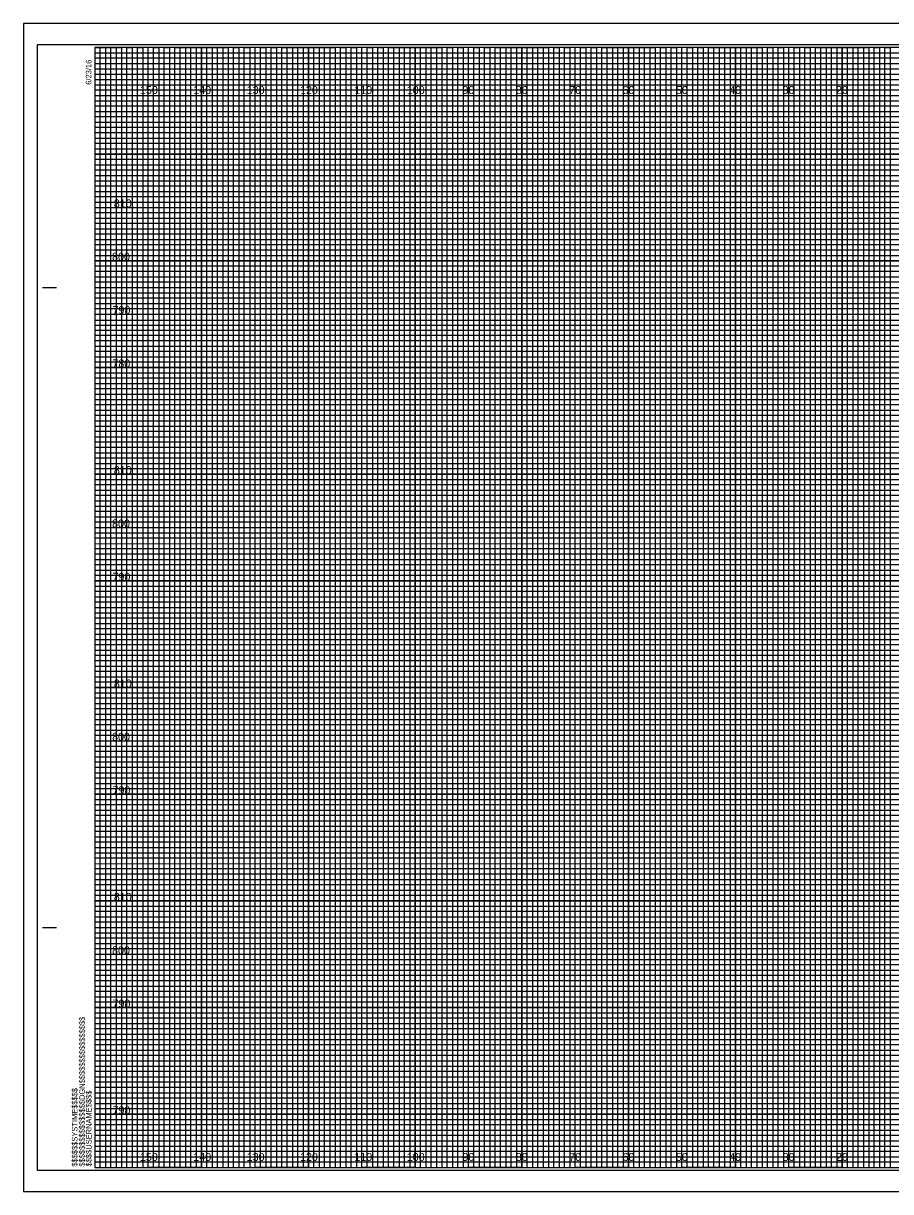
# Model space of a CAD drawing. Extents: x -13 to 323, y -4 to 214.
# Drawn here: x -13.4 to 149.1, y -4.5 to 214.5 of the extents above; entities that cross this region are included whole.
import ezdxf

# ---------------------------------------------------------------- set-up
doc = ezdxf.new("R2010")
doc.units = 0
for name, color, linetype in [('Exist Cross Section Cell', 7, 'Continuous'), ('Exist XS Center Line Elevation Label', 7, 'Continuous'), ('Exist XS Ground Line', 7, 'Continuous'), ('Prop CMT Pvmt Course 2', 7, 'Continuous'), ('Prop CMT Pvmt Course 3', 7, 'Continuous'), ('Prop CMT Pvmt Surface', 7, 'Continuous'), ('Prop CMT Shld Paved Course 1', 7, 'Continuous'), ('Prop CMT Shld Paved Course 3', 7, 'Continuous'), ('Prop CMT Subgrade Earthwork', 7, 'Continuous'), ('Scratch_Level_4', 7, 'Continuous'), ('Scratch_Level_7', 7, 'Continuous')]:
    doc.layers.add(name, color=color, linetype=linetype)

msp = doc.modelspace()

# ---------------------------------------------------------------- linework, layer by layer
at = {"layer": 'Exist XS Center Line Elevation Label'}
for points in [[(0, 210), (5, 210), (5, 0), (15, 0), (15, 210), (25, 210), (25, 0), (35, 0), (35, 210), (45, 210), (45, 0), (55, 0), (55, 210), (65, 210), (65, 0), (75, 0), (75, 210), (85, 210), (85, 0), (95, 0), (95, 210), (105, 210), (105, 0), (115, 0), (115, 210), (125, 210), (125, 0), (135, 0), (135, 210), (145, 210), (145, 0), (155, 0)], [(0, 205), (275, 205)], [(0, 185), (320, 185), (320, 195), (0, 195)], [(0, 165), (320, 165), (320, 175), (0, 175)], [(0, 145), (320, 145), (320, 155), (0, 155)], [(0, 125), (320, 125), (320, 135), (0, 135)], [(0, 105), (320, 105), (320, 115), (0, 115)], [(0, 85), (320, 85), (320, 95), (0, 95)], [(0, 65), (320, 65), (320, 75), (0, 75)], [(0, 45), (320, 45), (320, 55), (0, 55)], [(0, 25), (320, 25), (320, 35), (0, 35)], [(0, 5), (320, 5), (320, 15), (0, 15)]]:
    msp.add_lwpolyline(points, dxfattribs=at)
at = {"layer": 'Exist XS Ground Line'}
for p, q in [((10, 210), (0, 210)), ((10, 0), (10, 210)), ((30, 210), (20, 210)), ((20, 210), (20, 0)), ((30, 0), (30, 210)), ((50, 210), (40, 210)), ((40, 210), (40, 0)), ((50, 0), (50, 210)), ((70, 210), (60, 210)), ((60, 210), (60, 0)), ((70, 0), (70, 210)), ((90, 210), (80, 210)), ((80, 210), (80, 0)), ((90, 0), (90, 210)), ((110, 210), (100, 210)), ((100, 210), (100, 0)), ((110, 0), (110, 210)), ((130, 210), (120, 210)), ((120, 210), (120, 0)), ((130, 0), (130, 210)), ((150, 210), (140, 210)), ((140, 210), (140, 0)), ((20, 0), (10, 0)), ((40, 0), (30, 0)), ((60, 0), (50, 0)), ((80, 0), (70, 0)), ((100, 0), (90, 0)), ((120, 0), (110, 0)), ((140, 0), (130, 0))]:
    msp.add_line(p, q, dxfattribs=at)
for points in [[(0, 200), (320, 200), (320, 190), (0, 190)], [(0, 180), (320, 180), (320, 170), (0, 170)], [(0, 160), (320, 160), (320, 150), (0, 150)], [(0, 140), (320, 140), (320, 130), (0, 130)], [(0, 120), (320, 120), (320, 110), (0, 110)], [(0, 100), (320, 100), (320, 90), (0, 90)], [(0, 80), (320, 80), (320, 70), (0, 70)], [(0, 60), (320, 60), (320, 50), (0, 50)], [(0, 40), (320, 40), (320, 30), (0, 30)], [(0, 20), (320, 20), (320, 10), (0, 10)]]:
    msp.add_lwpolyline(points, dxfattribs=at)
at = {"layer": 'Prop CMT Pvmt Course 2'}
msp.add_lwpolyline([(-10.8, -0.5), (322.4, -0.5), (322.4, 210.5), (-10.8, 210.5)], close=True, dxfattribs=at)
at = {"layer": 'Prop CMT Pvmt Course 3'}
for p, q in [((10, 0), (10, 210)), ((20, 0), (20, 210)), ((30, 0), (30, 210)), ((40, 0), (40, 210)), ((50, 0), (50, 210)), ((60, 0), (60, 210)), ((70, 0), (70, 210)), ((80, 0), (80, 210)), ((90, 0), (90, 210)), ((100, 0), (100, 210)), ((110, 0), (110, 210)), ((120, 0), (120, 210)), ((130, 0), (130, 210)), ((140, 0), (140, 210)), ((0, 200), (320, 200)), ((0, 190), (320, 190)), ((0, 180), (320, 180)), ((0, 170), (320, 170)), ((0, 160), (320, 160)), ((0, 150), (320, 150)), ((0, 140), (320, 140)), ((0, 130), (320, 130)), ((0, 120), (320, 120)), ((0, 110), (320, 110)), ((0, 100), (320, 100)), ((0, 90), (320, 90)), ((0, 80), (320, 80)), ((0, 70), (320, 70)), ((0, 60), (320, 60)), ((0, 50), (320, 50)), ((0, 40), (320, 40)), ((0, 30), (320, 30)), ((0, 20), (320, 20)), ((0, 10), (320, 10))]:
    msp.add_line(p, q, dxfattribs=at)
at = {"layer": 'Prop CMT Shld Paved Course 1'}
for points in [[(0, 0), (1, 0), (1, 210), (2, 210), (2, 0)], [(2, 0), (3, 0), (3, 210), (4, 210), (4, 0)], [(5, 0), (6, 0), (6, 210), (7, 210), (7, 0)], [(7, 0), (8, 0), (8, 210), (9, 210), (9, 0)], [(10, 0), (11, 0), (11, 210), (12, 210), (12, 0)], [(12, 0), (13, 0), (13, 210), (14, 210), (14, 0)], [(15, 0), (16, 0), (16, 210), (17, 210), (17, 0)], [(17, 0), (18, 0), (18, 210), (19, 210), (19, 0)], [(20, 0), (21, 0), (21, 210), (22, 210), (22, 0)], [(22, 0), (23, 0), (23, 210), (24, 210), (24, 0)], [(25, 0), (26, 0), (26, 210), (27, 210), (27, 0)], [(27, 0), (28, 0), (28, 210), (29, 210), (29, 0)], [(30, 0), (31, 0), (31, 210), (32, 210), (32, 0)], [(32, 0), (33, 0), (33, 210), (34, 210), (34, 0)], [(35, 0), (36, 0), (36, 210), (37, 210), (37, 0)], [(37, 0), (38, 0), (38, 210), (39, 210), (39, 0)], [(40, 0), (41, 0), (41, 210), (42, 210), (42, 0)], [(42, 0), (43, 0), (43, 210), (44, 210), (44, 0)], [(45, 0), (46, 0), (46, 210), (47, 210), (47, 0)], [(47, 0), (48, 0), (48, 210), (49, 210), (49, 0)], [(50, 0), (51, 0), (51, 210), (52, 210), (52, 0)], [(52, 0), (53, 0), (53, 210), (54, 210), (54, 0)], [(55, 0), (56, 0), (56, 210), (57, 210), (57, 0)], [(57, 0), (58, 0), (58, 210), (59, 210), (59, 0)], [(60, 0), (61, 0), (61, 210), (62, 210), (62, 0)], [(62, 0), (63, 0), (63, 210), (64, 210), (64, 0)], [(65, 0), (66, 0), (66, 210), (67, 210), (67, 0)], [(67, 0), (68, 0), (68, 210), (69, 210), (69, 0)], [(70, 0), (71, 0), (71, 210), (72, 210), (72, 0)], [(72, 0), (73, 0), (73, 210), (74, 210), (74, 0)], [(75, 0), (76, 0), (76, 210), (77, 210), (77, 0)], [(77, 0), (78, 0), (78, 210), (79, 210), (79, 0)], [(80, 0), (81, 0), (81, 210), (82, 210), (82, 0)], [(82, 0), (83, 0), (83, 210), (84, 210), (84, 0)], [(85, 0), (86, 0), (86, 210), (87, 210), (87, 0)], [(87, 0), (88, 0), (88, 210), (89, 210), (89, 0)], [(90, 0), (91, 0), (91, 210), (92, 210), (92, 0)], [(92, 0), (93, 0), (93, 210), (94, 210), (94, 0)], [(95, 0), (96, 0), (96, 210), (97, 210), (97, 0)], [(97, 0), (98, 0), (98, 210), (99, 210), (99, 0)], [(100, 0), (101, 0), (101, 210), (102, 210), (102, 0)], [(102, 0), (103, 0), (103, 210), (104, 210), (104, 0)], [(105, 0), (106, 0), (106, 210), (107, 210), (107, 0)], [(107, 0), (108, 0), (108, 210), (109, 210), (109, 0)], [(110, 0), (111, 0), (111, 210), (112, 210), (112, 0)], [(112, 0), (113, 0), (113, 210), (114, 210), (114, 0)], [(115, 0), (116, 0), (116, 210), (117, 210), (117, 0)], [(117, 0), (118, 0), (118, 210), (119, 210), (119, 0)], [(120, 0), (121, 0), (121, 210), (122, 210), (122, 0)], [(122, 0), (123, 0), (123, 210), (124, 210), (124, 0)], [(125, 0), (126, 0), (126, 210), (127, 210), (127, 0)], [(127, 0), (128, 0), (128, 210), (129, 210), (129, 0)], [(130, 0), (131, 0), (131, 210), (132, 210), (132, 0)], [(132, 0), (133, 0), (133, 210), (134, 210), (134, 0)], [(135, 0), (136, 0), (136, 210), (137, 210), (137, 0)], [(137, 0), (138, 0), (138, 210), (139, 210), (139, 0)], [(140, 0), (141, 0), (141, 210), (142, 210), (142, 0)], [(142, 0), (143, 0), (143, 210), (144, 210), (144, 0)], [(145, 0), (146, 0), (146, 210), (147, 210), (147, 0)], [(147, 0), (148, 0), (148, 210), (149, 210), (149, 0)]]:
    msp.add_lwpolyline(points, dxfattribs=at)
at = {"layer": 'Prop CMT Shld Paved Course 3'}
msp.add_lwpolyline([(-13.4, -4.5), (323.3, -4.5), (323.3, 214.5), (-13.4, 214.5)], close=True, dxfattribs=at)
at = {"layer": 'Prop CMT Subgrade Earthwork'}
for p, q in [((323.3, 214.5), (-13.4, 214.5)), ((-13.4, 214.5), (-13.4, -4.5)), ((-13.4, -4.5), (323.3, -4.5))]:
    msp.add_line(p, q, dxfattribs=at)
at = {"layer": 'Scratch_Level_4'}
for p, q in [((0, 209), (260, 209)), ((260, 207.98), (0, 207.98)), ((0, 207.98), (0, 207)), ((0, 207), (260, 207)), ((260, 205.89), (0, 205.89)), ((0, 205.89), (0, 204)), ((0, 204), (320, 204))]:
    msp.add_line(p, q, dxfattribs=at)
for points in [[(0, 203), (270, 203), (320, 203), (320, 202), (0, 202)], [(0, 201), (320, 201), (320, 199), (0, 199)], [(0, 198), (320, 198), (320, 197), (0, 196.98)], [(0, 196), (320, 196), (320, 194), (0, 194)], [(0, 193), (320, 193), (320, 192), (0, 192)], [(0, 191), (320, 191), (320, 189), (0, 189)], [(0, 188), (320, 188), (320, 187), (0, 187)], [(0, 186), (320, 186), (320, 184), (0, 184)], [(0, 183), (320, 183), (320, 182), (0, 182)], [(0, 181), (320, 181), (320, 179), (0, 179)], [(0, 178), (320, 178), (320, 177), (0, 177)], [(0, 176), (320, 176), (320, 173.95), (320, 173), (320, 172), (0, 172)], [(0, 174), (320, 174), (320, 173), (0, 173)], [(0, 171), (320, 171), (320, 169), (0, 169.03)], [(0, 169.03), (320, 169), (320, 168), (0, 168)], [(0, 167), (320, 167), (320, 166), (0, 166)], [(0, 164), (320, 164), (320, 163), (0, 163)], [(0, 162), (320, 162), (320, 161), (0, 161)], [(-0.07, 158.89), (320, 158.89), (320, 157.88), (-0.07, 157.88)], [(0, 157), (320, 157), (320, 156), (0, 156)], [(0, 154), (320, 154), (320, 153), (0, 153)], [(0, 152), (320, 152), (320, 151), (0, 151)], [(0, 149), (320, 149), (320, 148), (0, 148)], [(0, 147), (320, 147), (320, 146), (0, 146)], [(0, 144), (320, 144), (320, 143), (0, 143)], [(0, 142), (320, 142), (320, 141), (0, 141)], [(0, 139), (320, 139), (319.99, 137.98), (0, 138)], [(0, 137), (320, 137), (320, 136), (0, 136)], [(0, 134), (320, 134), (320, 133), (0, 133)], [(0, 132), (320, 132), (320, 131), (0, 131)], [(0, 129), (320, 129), (320, 128), (0, 128)], [(0, 127), (320, 127), (320, 126), (0, 126)], [(0, 124), (320, 124), (320, 123), (0, 123)], [(0, 122), (320, 122), (320, 121), (0, 121)], [(0, 119), (320, 119), (320, 118), (0, 118)], [(0, 116.99), (320.07, 116.91), (320, 116), (0, 116)], [(0, 114), (320, 114), (320, 113), (0, 113)], [(0, 112), (320, 112), (320, 111), (0, 111)], [(0, 109), (320, 109), (320, 108), (0, 108)], [(0, 107), (320, 107), (320, 106), (0, 106)], [(0, 104), (320, 104), (320, 103), (0, 103)], [(0, 102), (320, 102), (320, 101), (0, 101)], [(0, 99), (320, 99), (320, 98), (0, 98)], [(0, 97), (320, 97), (320, 96), (0, 96)], [(0, 94), (320, 94), (320, 93), (0, 93)], [(0, 92), (320, 92), (320, 91), (0, 91)], [(0, 89), (320, 89), (320, 88), (0, 88)], [(0, 87), (320, 87), (320, 86), (0, 86)], [(0, 84), (320, 84), (320, 83), (0, 83)], [(0, 82), (320, 82), (320, 81), (0, 81)], [(0, 79), (320, 79), (319.99, 77.98), (0, 78)], [(0, 77), (320, 77), (320, 76), (0, 76)], [(0, 74), (320, 74), (320, 73), (0, 73)], [(0, 72), (320, 72), (320, 71), (0, 71)], [(0, 69), (320, 69), (320, 68), (0, 68)], [(0, 67), (320, 67), (320, 66), (0, 66)], [(0, 64), (320, 64), (320, 63), (0, 63)], [(0, 62), (320, 62), (320, 61), (0, 61)], [(0, 59), (320, 59), (320, 58), (0, 58)], [(0, 56.99), (320.07, 56.91), (320, 56), (0, 56)], [(0, 54), (320, 54), (320, 53), (0, 53)], [(0, 52), (320, 52), (320, 51), (0, 51)], [(0, 49), (320, 49), (320, 48), (0, 48)], [(0, 47), (320, 47), (320, 46), (0, 46)], [(0, 44), (320, 44), (320, 43), (0, 43)], [(0, 42), (320, 42), (320, 41), (0, 41)], [(0, 39), (320, 39), (320, 38), (0, 38)], [(0, 37), (320, 37), (320, 36), (0, 36)], [(0, 34), (320, 34), (320, 33), (0, 33)], [(0, 32), (320, 32), (320, 31), (0, 31)], [(0, 29), (320, 29), (320, 28), (0, 28)], [(0, 27), (320, 27), (320, 26), (0, 26)], [(0, 24), (320, 24), (320, 23), (0, 23)], [(0, 22), (320, 22), (320, 21), (0, 21)], [(0, 19), (320, 19), (320, 18), (0, 18)], [(0, 17), (320, 17), (320, 16), (0, 16)], [(0, 14), (320, 14), (320, 13), (0, 13)], [(0, 12), (320, 12), (320, 11), (0, 11)], [(0, 9), (320, 9), (320, 8), (0, 8)], [(0, 7), (320, 7), (320, 6), (0, 6)], [(0, 4), (320, 4), (320, 3), (0, 3)], [(0, 2), (320, 2), (320, 1), (0, 1)]]:
    msp.add_lwpolyline(points, dxfattribs=at)
at = {"layer": 'Scratch_Level_7'}
for p, q in [((-9.8, 165), (-7.3, 165)), ((-9.7, 165), (-7.2, 165)), ((-9.8, 45), (-7.3, 45)), ((-9.7, 45), (-7.2, 45)), ((0, 0), (0, 0)), ((0, 0), (0, 0)), ((0, 0), (0, 0)), ((0, 0), (0, 0)), ((0, 0), (0, 0)), ((0, 0), (0, 0)), ((0, 0), (0, 0))]:
    msp.add_line(p, q, dxfattribs=at)
msp.add_lwpolyline([(320, 210), (0, 210), (0, 0), (320, 0)], close=True, dxfattribs=at)

# ---------------------------------------------------------------- texts
at = {"layer": 'Exist Cross Section Cell'}
for s, p in [('150', (8.44, 201.25)), ('140', (18.44, 201.25)), ('130', (28.44, 201.25)), ('120', (38.44, 201.25)), ('110', (48.62, 201.25)), ('100', (58.44, 201.25)), ('90', (68.86, 201.25)), ('80', (78.86, 201.25)), ('70', (88.86, 201.25)), ('60', (98.86, 201.25)), ('50', (108.86, 201.25)), ('40', (118.86, 201.25)), ('30', (128.86, 201.25)), ('20', (138.86, 201.25)), ('150', (8.44, 1.25)), ('140', (18.44, 1.25)), ('130', (28.44, 1.25)), ('120', (38.44, 1.25)), ('110', (48.62, 1.25)), ('100', (58.44, 1.25)), ('90', (68.86, 1.25)), ('80', (78.86, 1.25)), ('70', (88.86, 1.25)), ('60', (98.86, 1.25)), ('50', (108.86, 1.25)), ('40', (118.86, 1.25)), ('30', (128.86, 1.25)), ('20', (138.86, 1.25))]:
    msp.add_text(s, height=1.5, dxfattribs=at).set_placement(p)
at = {"layer": 'Prop CMT Pvmt Surface'}
for s, p in [('810', (3.55, 180)), ('800', (3.22, 170)), ('790', (3.3, 160)), ('780', (3.28, 150)), ('810', (3.55, 130)), ('800', (3.22, 120)), ('790', (3.3, 110)), ('810', (3.55, 90)), ('800', (3.22, 80)), ('790', (3.3, 70)), ('810', (3.55, 50)), ('800', (3.22, 40)), ('790', (3.3, 30)), ('790', (3.3, 10))]:
    msp.add_text(s, height=1.5, dxfattribs=at).set_placement(p)
at = {"layer": 'Scratch_Level_7'}
for s, p in [('6/23/16', (-0.65, 203)), ('$$$$$$$$$$$$$$$$DGN$$$$$$$$$$$$$$$$', (-1.88, 0.18)), ('$$$$$$SYSTIME$$$$$', (-3.26, 0.18)), ('$$$$USERNAME$$$$', (-0.62, 0.23))]:
    msp.add_text(s, height=1.05, rotation=90, dxfattribs=at).set_placement(p)

doc.saveas('drawing.dxf')
